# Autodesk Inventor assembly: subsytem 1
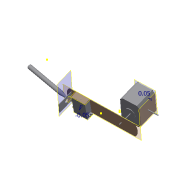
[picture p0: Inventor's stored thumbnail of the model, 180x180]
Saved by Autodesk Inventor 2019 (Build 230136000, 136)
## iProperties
Created: 2020-04
Part Number: subsytem 1
Document SubType Name: Assembly
Designer: Krupashree
Author: Krupashree
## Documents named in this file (3)
- A:\sec sem notes\Engg explorRION\MODELLING\subsytem 1.iam
- A:\sec sem notes\Engg explorRION\MODELLING\pen to holder.iam
- A:\sec sem notes\Engg explorRION\MODELLING\motor.ipt
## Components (2 placed, 2 different names)
1. pen to holder:1 [sub-assembly] — Mate:1
2. motor:1 — Mate:1
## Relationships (1: Mate 1)
- Mate:1: pen to holder:1 ↔ motor:1
